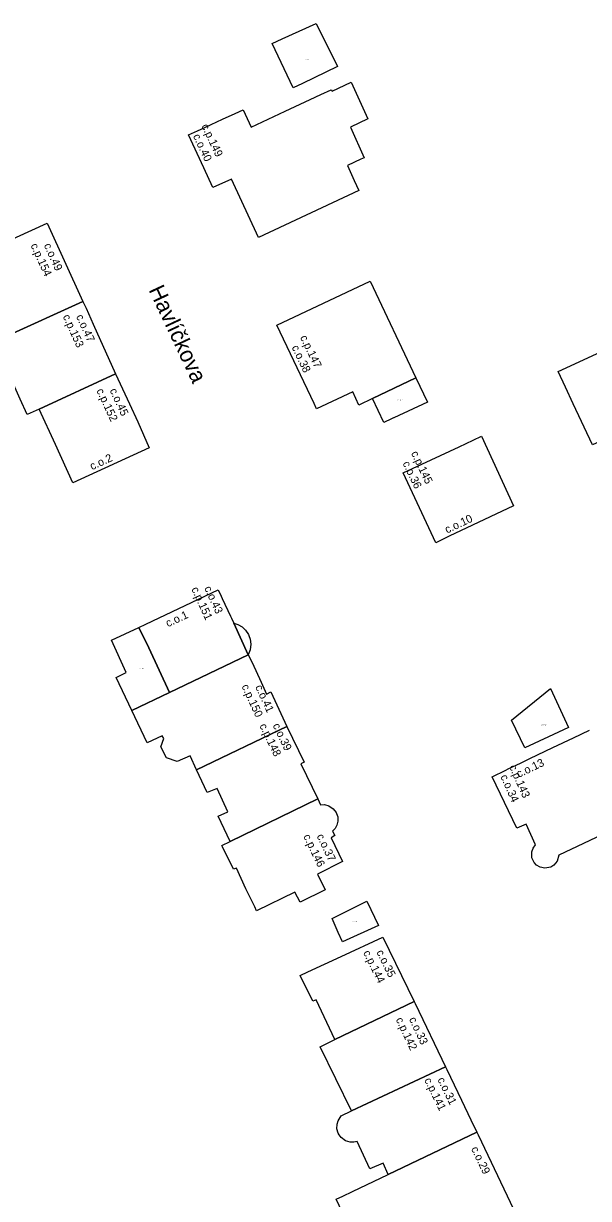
# Model space of a CAD drawing. Extents: x -600391 to -599491, y -1160176 to -1159402.
# Drawn here: x -600106.4 to -600035.9, y -1160089 to -1159942.1 of the extents above; entities that cross this region are included whole.
import ezdxf

# ---------------------------------------------------------------- set-up
doc = ezdxf.new("R2010")
doc.units = 0
for name, color, linetype in [('Level 10', 7, 'Continuous'), ('Level 11', 7, 'Continuous'), ('Level 12', 7, 'Continuous'), ('Level 24', 7, 'Continuous'), ('Level 25', 7, 'Continuous'), ('Level 61', 7, 'Continuous'), ('Level 62', 7, 'Continuous')]:
    doc.layers.add(name, color=color, linetype=linetype)

msp = doc.modelspace()

# ---------------------------------------------------------------- linework, layer by layer
at = {"layer": 'Level 61'}
for points in [[(-600074.14, -1159944.05), (-600069.9, -1159942.12)], [(-600069.9, -1159942.12), (-600067.24, -1159947.51)], [(-600075.38, -1159944.64), (-600074.14, -1159944.05)], [(-600072.78, -1159950.15), (-600075.38, -1159944.64)], [(-600067.24, -1159947.51), (-600071.62, -1159949.6)], [(-600071.62, -1159949.6), (-600072.78, -1159950.15)], [(-600069.29, -1159950.99), (-600068.01, -1159950.39)], [(-600068.01, -1159950.39), (-600067.89, -1159950.56)], [(-600067.89, -1159950.56), (-600065.53, -1159949.46)], [(-600065.53, -1159949.46), (-600063.45, -1159954.03)], [(-600073.76, -1159953.08), (-600070.64, -1159951.62)], [(-600070.64, -1159951.62), (-600069.29, -1159950.99)], [(-600081.57, -1159954.08), (-600080.01, -1159953.36)], [(-600080.01, -1159953.36), (-600079.02, -1159952.89)], [(-600079.02, -1159952.89), (-600078, -1159955.06)], [(-600078, -1159955.06), (-600073.76, -1159953.08)], [(-600083.71, -1159955.07), (-600081.57, -1159954.08)], [(-600063.45, -1159954.03), (-600065.6, -1159955.09)], [(-600085.82, -1159956.04), (-600084.71, -1159955.53)], [(-600083.92, -1159960.14), (-600085.82, -1159956.04)], [(-600084.71, -1159955.53), (-600083.71, -1159955.07)], [(-600065.6, -1159955.09), (-600063.9, -1159958.89)], [(-600064.3, -1159959.09), (-600065.99, -1159959.87)], [(-600063.9, -1159958.89), (-600064.3, -1159959.09)], [(-600082.78, -1159962.61), (-600083.92, -1159960.14)], [(-600065.99, -1159959.87), (-600065.15, -1159961.74)], [(-600080.45, -1159961.56), (-600082.78, -1159962.61)], [(-600077.11, -1159968.85), (-600080.45, -1159961.56)], [(-600065.15, -1159961.74), (-600064.58, -1159962.99)], [(-600064.58, -1159962.99), (-600077.11, -1159968.85)], [(-600115.98, -1159972.77), (-600103.46, -1159967.07)], [(-600103.46, -1159967.07), (-600099.03, -1159976.85)], [(-600074.79, -1159979.83), (-600063.15, -1159974.33)], [(-600063.15, -1159974.33), (-600057.44, -1159986.39)], [(-600108.73, -1159981.3), (-600099.03, -1159976.85)], [(-600099.03, -1159976.85), (-600108.73, -1159981.3)], [(-600099.03, -1159976.85), (-600098.62, -1159977.7)], [(-600098.62, -1159977.7), (-600097.72, -1159979.71)], [(-600097.72, -1159979.71), (-600094.93, -1159985.92)], [(-600070.16, -1159989.63), (-600074.79, -1159979.83)], [(-600039.67, -1159985.62), (-600030.13, -1159981.2)], [(-600038.77, -1159987.59), (-600039.67, -1159985.62)], [(-600094.93, -1159985.92), (-600104.49, -1159990.3)], [(-600104.49, -1159990.3), (-600094.93, -1159985.92)], [(-600094.93, -1159985.92), (-600093.21, -1159989.65)], [(-600057.44, -1159986.39), (-600062.88, -1159989)], [(-600062.88, -1159989), (-600057.44, -1159986.39)], [(-600057.44, -1159986.39), (-600055.99, -1159989.46)], [(-600065.31, -1159988.17), (-600069.84, -1159990.27)], [(-600064.57, -1159989.81), (-600065.31, -1159988.17)], [(-600037.8, -1159989.66), (-600038.77, -1159987.59)], [(-600105.99, -1159990.99), (-600106.86, -1159989.06)], [(-600093.21, -1159989.65), (-600092.16, -1159991.92)], [(-600069.84, -1159990.27), (-600070.16, -1159989.63)], [(-600062.88, -1159989), (-600064.57, -1159989.81)], [(-600061.46, -1159992), (-600062.88, -1159989)], [(-600055.99, -1159989.46), (-600060.21, -1159991.42)], [(-600035.41, -1159994.76), (-600037.8, -1159989.66)], [(-600104.49, -1159990.3), (-600105.99, -1159990.99)], [(-600102.45, -1159994.72), (-600104.49, -1159990.3)], [(-600060.47, -1159991.54), (-600061.46, -1159992)], [(-600060.22, -1159991.42), (-600060.47, -1159991.54)], [(-600060.21, -1159991.42), (-600060.22, -1159991.42)], [(-600092.16, -1159991.92), (-600090.72, -1159995.14)], [(-600052.06, -1159995.01), (-600050.3, -1159994.19)], [(-600050.3, -1159994.19), (-600049.27, -1159993.71)], [(-600049.27, -1159993.71), (-600045.25, -1160002.42)], [(-600100.27, -1159999.53), (-600102.45, -1159994.72)], [(-600090.72, -1159995.14), (-600100.27, -1159999.53)], [(-600059.03, -1159998.26), (-600052.06, -1159995.01)], [(-600054.94, -1160007.01), (-600059.03, -1159998.26)], [(-600045.25, -1160002.42), (-600053.29, -1160006.21)], [(-600053.29, -1160006.21), (-600054.94, -1160007.01)], [(-600091.15, -1160017.18), (-600082.11, -1160012.92)], [(-600082.11, -1160012.92), (-600081.76, -1160013.69)], [(-600081.76, -1160013.69), (-600081.63, -1160013.97)], [(-600081.63, -1160013.97), (-600080.59, -1160016.19)], [(-600080.59, -1160016.19), (-600080.48, -1160016.43)], [(-600080.48, -1160016.43), (-600080.19, -1160017.07)], [(-600095.44, -1160019.2), (-600092.02, -1160017.59)], [(-600092.02, -1160017.59), (-600091.15, -1160017.18)], [(-600090.79, -1160020.16), (-600092.02, -1160017.59)], [(-600092.02, -1160017.59), (-600090.79, -1160020.16)], [(-600080.19, -1160017.07), (-600078.37, -1160021.03)], [(-600078.37, -1160021.03), (-600080.19, -1160017.07)], [(-600080.19, -1160017.07), (-600079.69, -1160017.23)], [(-600079.69, -1160017.23), (-600079.15, -1160017.53)], [(-600079.15, -1160017.53), (-600078.71, -1160017.95)], [(-600078.71, -1160017.95), (-600078.34, -1160018.5)], [(-600093.6, -1160023.24), (-600095.44, -1160019.2)], [(-600078.34, -1160018.5), (-600078.29, -1160018.6)], [(-600078.29, -1160018.6), (-600078.13, -1160019.05)], [(-600078.13, -1160019.05), (-600078.04, -1160019.69)], [(-600088.21, -1160025.75), (-600090.79, -1160020.16)], [(-600090.79, -1160020.16), (-600088.21, -1160025.75)], [(-600078.12, -1160020.41), (-600078.37, -1160021.03)], [(-600078.04, -1160019.69), (-600078.12, -1160020.41)], [(-600078.37, -1160021.03), (-600088.21, -1160025.75)], [(-600088.21, -1160025.75), (-600078.37, -1160021.03)], [(-600078.37, -1160021.03), (-600077.9, -1160021.98)], [(-600077.9, -1160021.98), (-600076.76, -1160024.42)], [(-600094.87, -1160023.84), (-600093.6, -1160023.24)], [(-600092.9, -1160027.99), (-600094.87, -1160023.84)], [(-600076.76, -1160024.42), (-600076.11, -1160025.95)], [(-600045.5, -1160029.19), (-600040.64, -1160025.25)], [(-600040.64, -1160025.25), (-600038.38, -1160030.09)], [(-600092.9, -1160027.99), (-600088.21, -1160025.75)], [(-600088.21, -1160025.75), (-600092.9, -1160027.99)], [(-600076.11, -1160025.95), (-600075.54, -1160025.64)], [(-600075.54, -1160025.64), (-600073.54, -1160030)], [(-600091.01, -1160032.04), (-600092.9, -1160027.99)], [(-600043.86, -1160032.63), (-600045.5, -1160029.19)], [(-600089.11, -1160031.13), (-600091.01, -1160032.04)], [(-600088.9, -1160031.49), (-600089.11, -1160031.13)], [(-600073.54, -1160030), (-600084.82, -1160035.38)], [(-600084.82, -1160035.38), (-600073.54, -1160030)], [(-600073.54, -1160030), (-600071.41, -1160034.45)], [(-600040.91, -1160031.26), (-600043.86, -1160032.63)], [(-600038.38, -1160030.09), (-600040.91, -1160031.26)], [(-600037.77, -1160031.38), (-600035.79, -1160030.42)], [(-600089.3, -1160032.53), (-600088.9, -1160031.49)], [(-600088.59, -1160033.88), (-600089.3, -1160032.53)], [(-600043.21, -1160033.99), (-600040.35, -1160032.62)], [(-600040.35, -1160032.62), (-600037.77, -1160031.38)], [(-600087.26, -1160034.36), (-600088.59, -1160033.88)], [(-600085.63, -1160033.66), (-600087.26, -1160034.36)], [(-600084.82, -1160035.38), (-600085.63, -1160033.66)], [(-600044.06, -1160034.4), (-600043.21, -1160033.99)], [(-600083.5, -1160038.24), (-600084.82, -1160035.38)], [(-600071.41, -1160034.45), (-600071.82, -1160034.65)], [(-600071.82, -1160034.65), (-600069.7, -1160039.03)], [(-600047.91, -1160036.25), (-600046.23, -1160035.44)], [(-600046.23, -1160035.44), (-600045.92, -1160035.29)], [(-600045.92, -1160035.29), (-600044.4, -1160034.56)], [(-600044.4, -1160034.56), (-600044.06, -1160034.4)], [(-600044.84, -1160042.68), (-600047.91, -1160036.25)], [(-600082.24, -1160037.71), (-600083.5, -1160038.24)], [(-600080.93, -1160040.64), (-600082.24, -1160037.71)], [(-600080.61, -1160044.37), (-600069.7, -1160039.03)], [(-600069.7, -1160039.03), (-600080.61, -1160044.37)], [(-600069.7, -1160039.03), (-600069.35, -1160039.75)], [(-600069.35, -1160039.75), (-600068.84, -1160039.74)], [(-600068.84, -1160039.74), (-600068.31, -1160039.89)], [(-600068.31, -1160039.89), (-600067.76, -1160040.25)], [(-600082.12, -1160041.19), (-600080.93, -1160040.64)], [(-600080.61, -1160044.37), (-600082.12, -1160041.19)], [(-600067.76, -1160040.25), (-600067.39, -1160040.74)], [(-600067.39, -1160040.74), (-600067.34, -1160040.85)], [(-600067.34, -1160040.85), (-600067.2, -1160041.28)], [(-600067.2, -1160041.28), (-600067.18, -1160041.81)], [(-600067.51, -1160042.73), (-600067.84, -1160043.08)], [(-600067.3, -1160042.32), (-600067.51, -1160042.73)], [(-600067.18, -1160041.81), (-600067.3, -1160042.32)], [(-600043.68, -1160042.2), (-600044.84, -1160042.68)], [(-600042.51, -1160044.75), (-600043.68, -1160042.2)], [(-600030.36, -1160041.68), (-600039.6, -1160046.08)], [(-600081.66, -1160044.86), (-600080.61, -1160044.37)], [(-600067.55, -1160043.61), (-600068.03, -1160043.9)], [(-600068.03, -1160043.9), (-600066.61, -1160046.87)], [(-600067.84, -1160043.08), (-600067.55, -1160043.61)], [(-600081.58, -1160045.02), (-600081.66, -1160044.86)], [(-600080.2, -1160047.82), (-600081.58, -1160045.02)], [(-600042.99, -1160045.66), (-600042.82, -1160045.17)], [(-600042.98, -1160046.39), (-600042.99, -1160045.66)], [(-600042.82, -1160045.17), (-600042.51, -1160044.75)], [(-600066.61, -1160046.87), (-600069.71, -1160048.42)], [(-600042.69, -1160046.98), (-600042.98, -1160046.39)], [(-600042.37, -1160047.33), (-600042.69, -1160046.98)], [(-600041.94, -1160047.56), (-600042.37, -1160047.33)], [(-600040.22, -1160047.29), (-600040.59, -1160047.54)], [(-600039.81, -1160046.83), (-600040.22, -1160047.29)], [(-600039.6, -1160046.08), (-600039.81, -1160046.83)], [(-600079.83, -1160047.68), (-600080.2, -1160047.82)], [(-600078.68, -1160050.25), (-600079.83, -1160047.68)], [(-600069.71, -1160048.42), (-600068.75, -1160050.38)], [(-600041.35, -1160047.69), (-600041.94, -1160047.56)], [(-600040.59, -1160047.54), (-600041.35, -1160047.69)], [(-600077.57, -1160052.51), (-600078.68, -1160050.25)], [(-600068.75, -1160050.38), (-600071.91, -1160051.95)], [(-600072.55, -1160050.69), (-600077.33, -1160053.03)], [(-600071.91, -1160051.95), (-600072.55, -1160050.69)], [(-600067.89, -1160053.97), (-600063.56, -1160051.83)], [(-600063.56, -1160051.83), (-600062.13, -1160054.84)], [(-600077.33, -1160053.03), (-600077.57, -1160052.51)], [(-600067.14, -1160055.71), (-600067.89, -1160053.97)], [(-600066.62, -1160056.9), (-600067.14, -1160055.71)], [(-600062.13, -1160054.84), (-600066.62, -1160056.9)], [(-600066.77, -1160058.74), (-600061.59, -1160056.32)], [(-600061.59, -1160056.32), (-600057.65, -1160064.37)], [(-600070.95, -1160060.65), (-600066.77, -1160058.74)], [(-600071.88, -1160061.08), (-600070.95, -1160060.65)], [(-600070.32, -1160064.29), (-600071.88, -1160061.08)], [(-600069.9, -1160064.13), (-600070.32, -1160064.29)], [(-600067.55, -1160069.09), (-600069.9, -1160064.13)], [(-600057.65, -1160064.37), (-600067.55, -1160069.09)], [(-600067.55, -1160069.09), (-600057.65, -1160064.37)], [(-600057.65, -1160064.37), (-600057.55, -1160064.58)], [(-600057.55, -1160064.58), (-600053.74, -1160072.53)], [(-600069.41, -1160070.01), (-600067.55, -1160069.09)], [(-600065.47, -1160078.02), (-600069.41, -1160070.01)], [(-600065.47, -1160078.02), (-600053.74, -1160072.53)], [(-600053.74, -1160072.53), (-600065.47, -1160078.02)], [(-600053.74, -1160072.53), (-600053.6, -1160072.83)], [(-600053.6, -1160072.83), (-600051.76, -1160076.66)], [(-600051.76, -1160076.66), (-600050.58, -1160079.14)], [(-600066.78, -1160078.63), (-600065.47, -1160078.02)], [(-600067.3, -1160080.25), (-600067.29, -1160079.69)], [(-600067.29, -1160079.69), (-600067.15, -1160079.26)], [(-600067.15, -1160079.26), (-600066.78, -1160078.63)], [(-600050.58, -1160079.14), (-600049.84, -1160080.67)], [(-600067.14, -1160080.81), (-600067.3, -1160080.25)], [(-600067.03, -1160081.02), (-600067.14, -1160080.81)], [(-600066.76, -1160081.36), (-600067.03, -1160081.02)], [(-600049.84, -1160080.67), (-600060.91, -1160085.95)], [(-600060.91, -1160085.95), (-600049.84, -1160080.67)], [(-600049.84, -1160080.67), (-600049.69, -1160081.01)], [(-600049.69, -1160081.01), (-600045.26, -1160090.3)], [(-600066.22, -1160081.75), (-600066.76, -1160081.36)], [(-600065.65, -1160081.92), (-600066.22, -1160081.75)], [(-600065.18, -1160081.92), (-600065.65, -1160081.92)], [(-600064.78, -1160081.84), (-600065.18, -1160081.92)], [(-600063.21, -1160085.28), (-600064.78, -1160081.84)], [(-600061.53, -1160084.55), (-600063.21, -1160085.28)], [(-600060.91, -1160085.95), (-600061.53, -1160084.55)], [(-600065.37, -1160088.09), (-600060.91, -1160085.95)], [(-600066.58, -1160088.67), (-600065.37, -1160088.09)], [(-600067.38, -1160089.05), (-600066.58, -1160088.67)]]:
    msp.add_lwpolyline(points, dxfattribs=at)
at = {"layer": 'Level 62'}
for points in [[(-600071.62, -1159949.6), (-600072.78, -1159950.15), (-600075.38, -1159944.64), (-600074.14, -1159944.05), (-600069.9, -1159942.12), (-600067.24, -1159947.51), (-600071.62, -1159949.6)], [(-600083.92, -1159960.14), (-600085.82, -1159956.04), (-600084.71, -1159955.53), (-600083.71, -1159955.07), (-600081.57, -1159954.08), (-600080.01, -1159953.36), (-600079.02, -1159952.89), (-600078, -1159955.06), (-600073.76, -1159953.08), (-600070.64, -1159951.62), (-600069.29, -1159950.99), (-600068.01, -1159950.39), (-600067.89, -1159950.56), (-600065.53, -1159949.46), (-600063.45, -1159954.03), (-600065.6, -1159955.09), (-600063.9, -1159958.89), (-600064.3, -1159959.09), (-600065.99, -1159959.87), (-600065.15, -1159961.74), (-600064.58, -1159962.99), (-600077.11, -1159968.85), (-600080.45, -1159961.56), (-600082.78, -1159962.61), (-600083.92, -1159960.14)], [(-600108.73, -1159981.3), (-600111.13, -1159976.02), (-600111.73, -1159974.7), (-600114.51, -1159975.96), (-600115.98, -1159972.77), (-600103.46, -1159967.07), (-600099.03, -1159976.85), (-600108.73, -1159981.3)], [(-600062.88, -1159989), (-600064.57, -1159989.81), (-600065.31, -1159988.17), (-600069.84, -1159990.27), (-600070.16, -1159989.63), (-600074.79, -1159979.83), (-600063.15, -1159974.33), (-600057.44, -1159986.39), (-600062.88, -1159989)], [(-600108.73, -1159981.3), (-600099.03, -1159976.85), (-600098.62, -1159977.7), (-600097.72, -1159979.71), (-600094.93, -1159985.92), (-600104.49, -1159990.3), (-600105.99, -1159990.99), (-600106.86, -1159989.06), (-600109.9, -1159982.33), (-600110.09, -1159981.93), (-600108.73, -1159981.3)], [(-600038.77, -1159987.59), (-600039.67, -1159985.62), (-600030.13, -1159981.2), (-600025.9, -1159990.41), (-600035.41, -1159994.76), (-600037.8, -1159989.66), (-600038.77, -1159987.59)], [(-600094.93, -1159985.92), (-600093.21, -1159989.65), (-600092.16, -1159991.92), (-600090.72, -1159995.14), (-600100.27, -1159999.53), (-600102.45, -1159994.72), (-600104.49, -1159990.3), (-600094.93, -1159985.92)], [(-600062.88, -1159989), (-600057.44, -1159986.39), (-600055.99, -1159989.46), (-600060.21, -1159991.42), (-600060.22, -1159991.42), (-600060.47, -1159991.54), (-600061.46, -1159992), (-600062.88, -1159989)], [(-600049.27, -1159993.71), (-600045.25, -1160002.42), (-600053.29, -1160006.21), (-600054.94, -1160007.01), (-600059.03, -1159998.26), (-600052.06, -1159995.01), (-600050.3, -1159994.19), (-600049.27, -1159993.71)], [(-600080.59, -1160016.19), (-600080.48, -1160016.43), (-600080.19, -1160017.07), (-600078.37, -1160021.03), (-600088.21, -1160025.75), (-600090.79, -1160020.16), (-600092.02, -1160017.59), (-600091.15, -1160017.18), (-600082.11, -1160012.92), (-600081.76, -1160013.69), (-600081.63, -1160013.97), (-600080.59, -1160016.19)], [(-600092.9, -1160027.99), (-600094.87, -1160023.84), (-600093.6, -1160023.24), (-600095.44, -1160019.2), (-600092.02, -1160017.59), (-600090.79, -1160020.16), (-600088.21, -1160025.75), (-600092.9, -1160027.99)], [(-600078.37, -1160021.03), (-600080.19, -1160017.07), (-600079.69, -1160017.23), (-600079.15, -1160017.53), (-600078.71, -1160017.95), (-600078.34, -1160018.5), (-600078.29, -1160018.6), (-600078.13, -1160019.05), (-600078.04, -1160019.69), (-600078.12, -1160020.41), (-600078.37, -1160021.03)], [(-600076.76, -1160024.42), (-600076.11, -1160025.95), (-600075.54, -1160025.64), (-600073.54, -1160030), (-600084.82, -1160035.38), (-600085.63, -1160033.66), (-600087.26, -1160034.36), (-600088.59, -1160033.88), (-600089.3, -1160032.53), (-600088.9, -1160031.49), (-600089.11, -1160031.13), (-600091.01, -1160032.04), (-600092.9, -1160027.99), (-600088.21, -1160025.75), (-600078.37, -1160021.03), (-600077.9, -1160021.98), (-600076.76, -1160024.42)], [(-600040.91, -1160031.26), (-600043.86, -1160032.63), (-600045.5, -1160029.19), (-600040.64, -1160025.25), (-600038.38, -1160030.09), (-600040.91, -1160031.26)], [(-600084.82, -1160035.38), (-600073.54, -1160030), (-600071.41, -1160034.45), (-600071.82, -1160034.65), (-600069.7, -1160039.03), (-600080.61, -1160044.37), (-600082.12, -1160041.19), (-600080.93, -1160040.64), (-600082.24, -1160037.71), (-600083.5, -1160038.24), (-600084.82, -1160035.38)], [(-600043.21, -1160033.99), (-600040.35, -1160032.62), (-600037.77, -1160031.38), (-600035.79, -1160030.42)], [(-600030.36, -1160041.68), (-600039.6, -1160046.08), (-600039.81, -1160046.83), (-600040.22, -1160047.29), (-600040.59, -1160047.54), (-600041.35, -1160047.69), (-600041.94, -1160047.56), (-600042.37, -1160047.33), (-600042.69, -1160046.98), (-600042.98, -1160046.39), (-600042.99, -1160045.66), (-600042.82, -1160045.17), (-600042.51, -1160044.75), (-600043.68, -1160042.2), (-600044.84, -1160042.68), (-600047.91, -1160036.25), (-600046.23, -1160035.44), (-600045.92, -1160035.29), (-600044.4, -1160034.56), (-600044.06, -1160034.4), (-600043.21, -1160033.99)], [(-600078.68, -1160050.25), (-600079.83, -1160047.68), (-600080.2, -1160047.82), (-600081.58, -1160045.02), (-600081.66, -1160044.86), (-600080.61, -1160044.37), (-600069.7, -1160039.03), (-600069.35, -1160039.75), (-600068.84, -1160039.74), (-600068.31, -1160039.89), (-600067.76, -1160040.25), (-600067.39, -1160040.74), (-600067.34, -1160040.85), (-600067.2, -1160041.28), (-600067.18, -1160041.81), (-600067.3, -1160042.32), (-600067.51, -1160042.73), (-600067.84, -1160043.08), (-600067.55, -1160043.61), (-600068.03, -1160043.9), (-600066.61, -1160046.87), (-600069.71, -1160048.42), (-600068.75, -1160050.38), (-600071.91, -1160051.95), (-600072.55, -1160050.69), (-600077.33, -1160053.03), (-600077.57, -1160052.51), (-600078.68, -1160050.25)], [(-600067.89, -1160053.97), (-600063.56, -1160051.83), (-600062.13, -1160054.84), (-600066.62, -1160056.9), (-600067.14, -1160055.71), (-600067.89, -1160053.97)], [(-600066.77, -1160058.74), (-600061.59, -1160056.32), (-600057.65, -1160064.37), (-600067.55, -1160069.09), (-600069.9, -1160064.13), (-600070.32, -1160064.29), (-600071.88, -1160061.08), (-600070.95, -1160060.65), (-600066.77, -1160058.74)], [(-600053.74, -1160072.53), (-600065.47, -1160078.02), (-600069.41, -1160070.01), (-600067.55, -1160069.09), (-600057.65, -1160064.37), (-600057.55, -1160064.58), (-600053.74, -1160072.53)], [(-600053.74, -1160072.53), (-600053.6, -1160072.83), (-600051.76, -1160076.66), (-600050.58, -1160079.14), (-600049.84, -1160080.67), (-600060.91, -1160085.95), (-600061.53, -1160084.55), (-600063.21, -1160085.28), (-600064.78, -1160081.84), (-600065.18, -1160081.92), (-600065.65, -1160081.92), (-600066.22, -1160081.75), (-600066.76, -1160081.36), (-600067.03, -1160081.02), (-600067.14, -1160080.81), (-600067.3, -1160080.25), (-600067.29, -1160079.69), (-600067.15, -1160079.26), (-600066.78, -1160078.63), (-600065.47, -1160078.02), (-600053.74, -1160072.53)], [(-600050.02, -1160092.59), (-600050.67, -1160092.9), (-600051.12, -1160093.12), (-600052.82, -1160093.95), (-600053.23, -1160094.15), (-600052.67, -1160095.26), (-600059.45, -1160098.53), (-600063.13, -1160090.99), (-600065.86, -1160092.32), (-600067.38, -1160089.05), (-600066.58, -1160088.67), (-600065.37, -1160088.09), (-600060.91, -1160085.95), (-600049.84, -1160080.67), (-600049.69, -1160081.01), (-600045.26, -1160090.3), (-600049.27, -1160092.22), (-600050.02, -1160092.59)]]:
    msp.add_lwpolyline(points, dxfattribs=at)

# ---------------------------------------------------------------- texts
at = {"layer": 'Level 10'}
for s, rotation, p in [('c.o.40', 295.1121, (-600085.3, -1159956.18)), ('c.o.49', 294.3738, (-600103.91, -1159969.83)), ('c.o.47', 294.3174, (-600099.89, -1159978.73)), ('c.o.38', 295.4094, (-600072.98, -1159982.58)), ('c.o.45', 294.7839, (-600095.7, -1159987.97)), ('c.o.2', 24.6891, (-600097.87, -1159997.96)), ('c.o.36', 295.5119, (-600059.13, -1159997.08)), ('c.o.10', 25.3478, (-600053.55, -1160005.88)), ('c.o.43', 294.3866, (-600083.89, -1160012.68)), ('c.o.1', 24.9224, (-600088.4, -1160017.58)), ('c.o.41', 294.6403, (-600077.53, -1160025.03)), ('c.o.39', 295.5759, (-600075.35, -1160029.84)), ('c.o.13', 25.6451, (-600044.61, -1160036.41)), ('c.o.34', 293.9479, (-600046.92, -1160036.23)), ('c.o.37', 295.5503, (-600069.86, -1160043.67)), ('c.o.35', 296.0321, (-600062.4, -1160058.17)), ('c.o.33', 295.0889, (-600058.33, -1160066.55)), ('c.o.31', 295.9578, (-600054.78, -1160074.1)), ('c.o.29', 295.4939, (-600050.58, -1160082.75))]:
    msp.add_text(s, height=1, rotation=rotation, dxfattribs=at).set_placement(p)
at = {"layer": 'Level 11'}
msp.add_text('Havlíčkova', height=2, rotation=295.1507, dxfattribs=at).set_placement((-600090.84, -1159975.4))
at = {"layer": 'Level 12'}
for s, rotation, p in [('c.p.149', 295.1121, (-600084.24, -1159954.93)), ('c.p.154', 294.3738, (-600105.57, -1159969.84)), ('c.p.153', 294.3174, (-600101.55, -1159978.73)), ('c.p.147', 295.4094, (-600071.93, -1159981.34)), ('c.p.152', 294.7839, (-600097.35, -1159987.99)), ('c.p.145', 295.5119, (-600058.08, -1159995.82)), ('c.p.151', 294.3866, (-600085.5, -1160012.79)), ('c.p.150', 294.6403, (-600079.23, -1160024.95)), ('c.p.148', 295.5759, (-600077, -1160029.88)), ('c.p.143', 293.9479, (-600045.83, -1160035.01)), ('c.p.146', 295.5503, (-600071.53, -1160043.7)), ('c.p.144', 296.0321, (-600064.06, -1160058.23)), ('c.p.142', 295.0889, (-600059.98, -1160066.59)), ('c.p.141', 295.9578, (-600056.43, -1160074.16))]:
    msp.add_text(s, height=1, rotation=rotation, dxfattribs=at).set_placement(p)
at = {"layer": 'Level 24'}
for s, p in [('c.z.362', (-600071.25, -1159946.65)), ('c.z.368', (-600091.92, -1160022.77))]:
    msp.add_text(s, height=0.1, dxfattribs=at).set_placement(p)
at = {"layer": 'Level 25'}
for s, p in [('c.pp.147_A', (-600059.75, -1159989.22)), ('c.pp.143_B', (-600041.85, -1160029.83)), ('c.pp.144_A', (-600065.34, -1160054.38))]:
    msp.add_text(s, height=0.1, dxfattribs=at).set_placement(p)

doc.saveas('drawing.dxf')
